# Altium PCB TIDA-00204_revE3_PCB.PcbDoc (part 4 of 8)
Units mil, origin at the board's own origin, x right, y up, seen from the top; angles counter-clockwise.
Board outline 4600 x 3740 mil, 8 copper layers (TopLayer - S1 (.GTL), MidLayer1 - S2 (.G1), MidLayer2 - S3 (.G2), MidLayer3 - S4 (.G3), MidLayer4 - S5 (.G4), MidLayer5 - S6 (.G5), MidLayer6 - S7 (.G6), BottomLayer - S8 (.GBL)), stack 58.938 mil thick; 536 components, 354 nets, 2015 pads, 1067 vias.
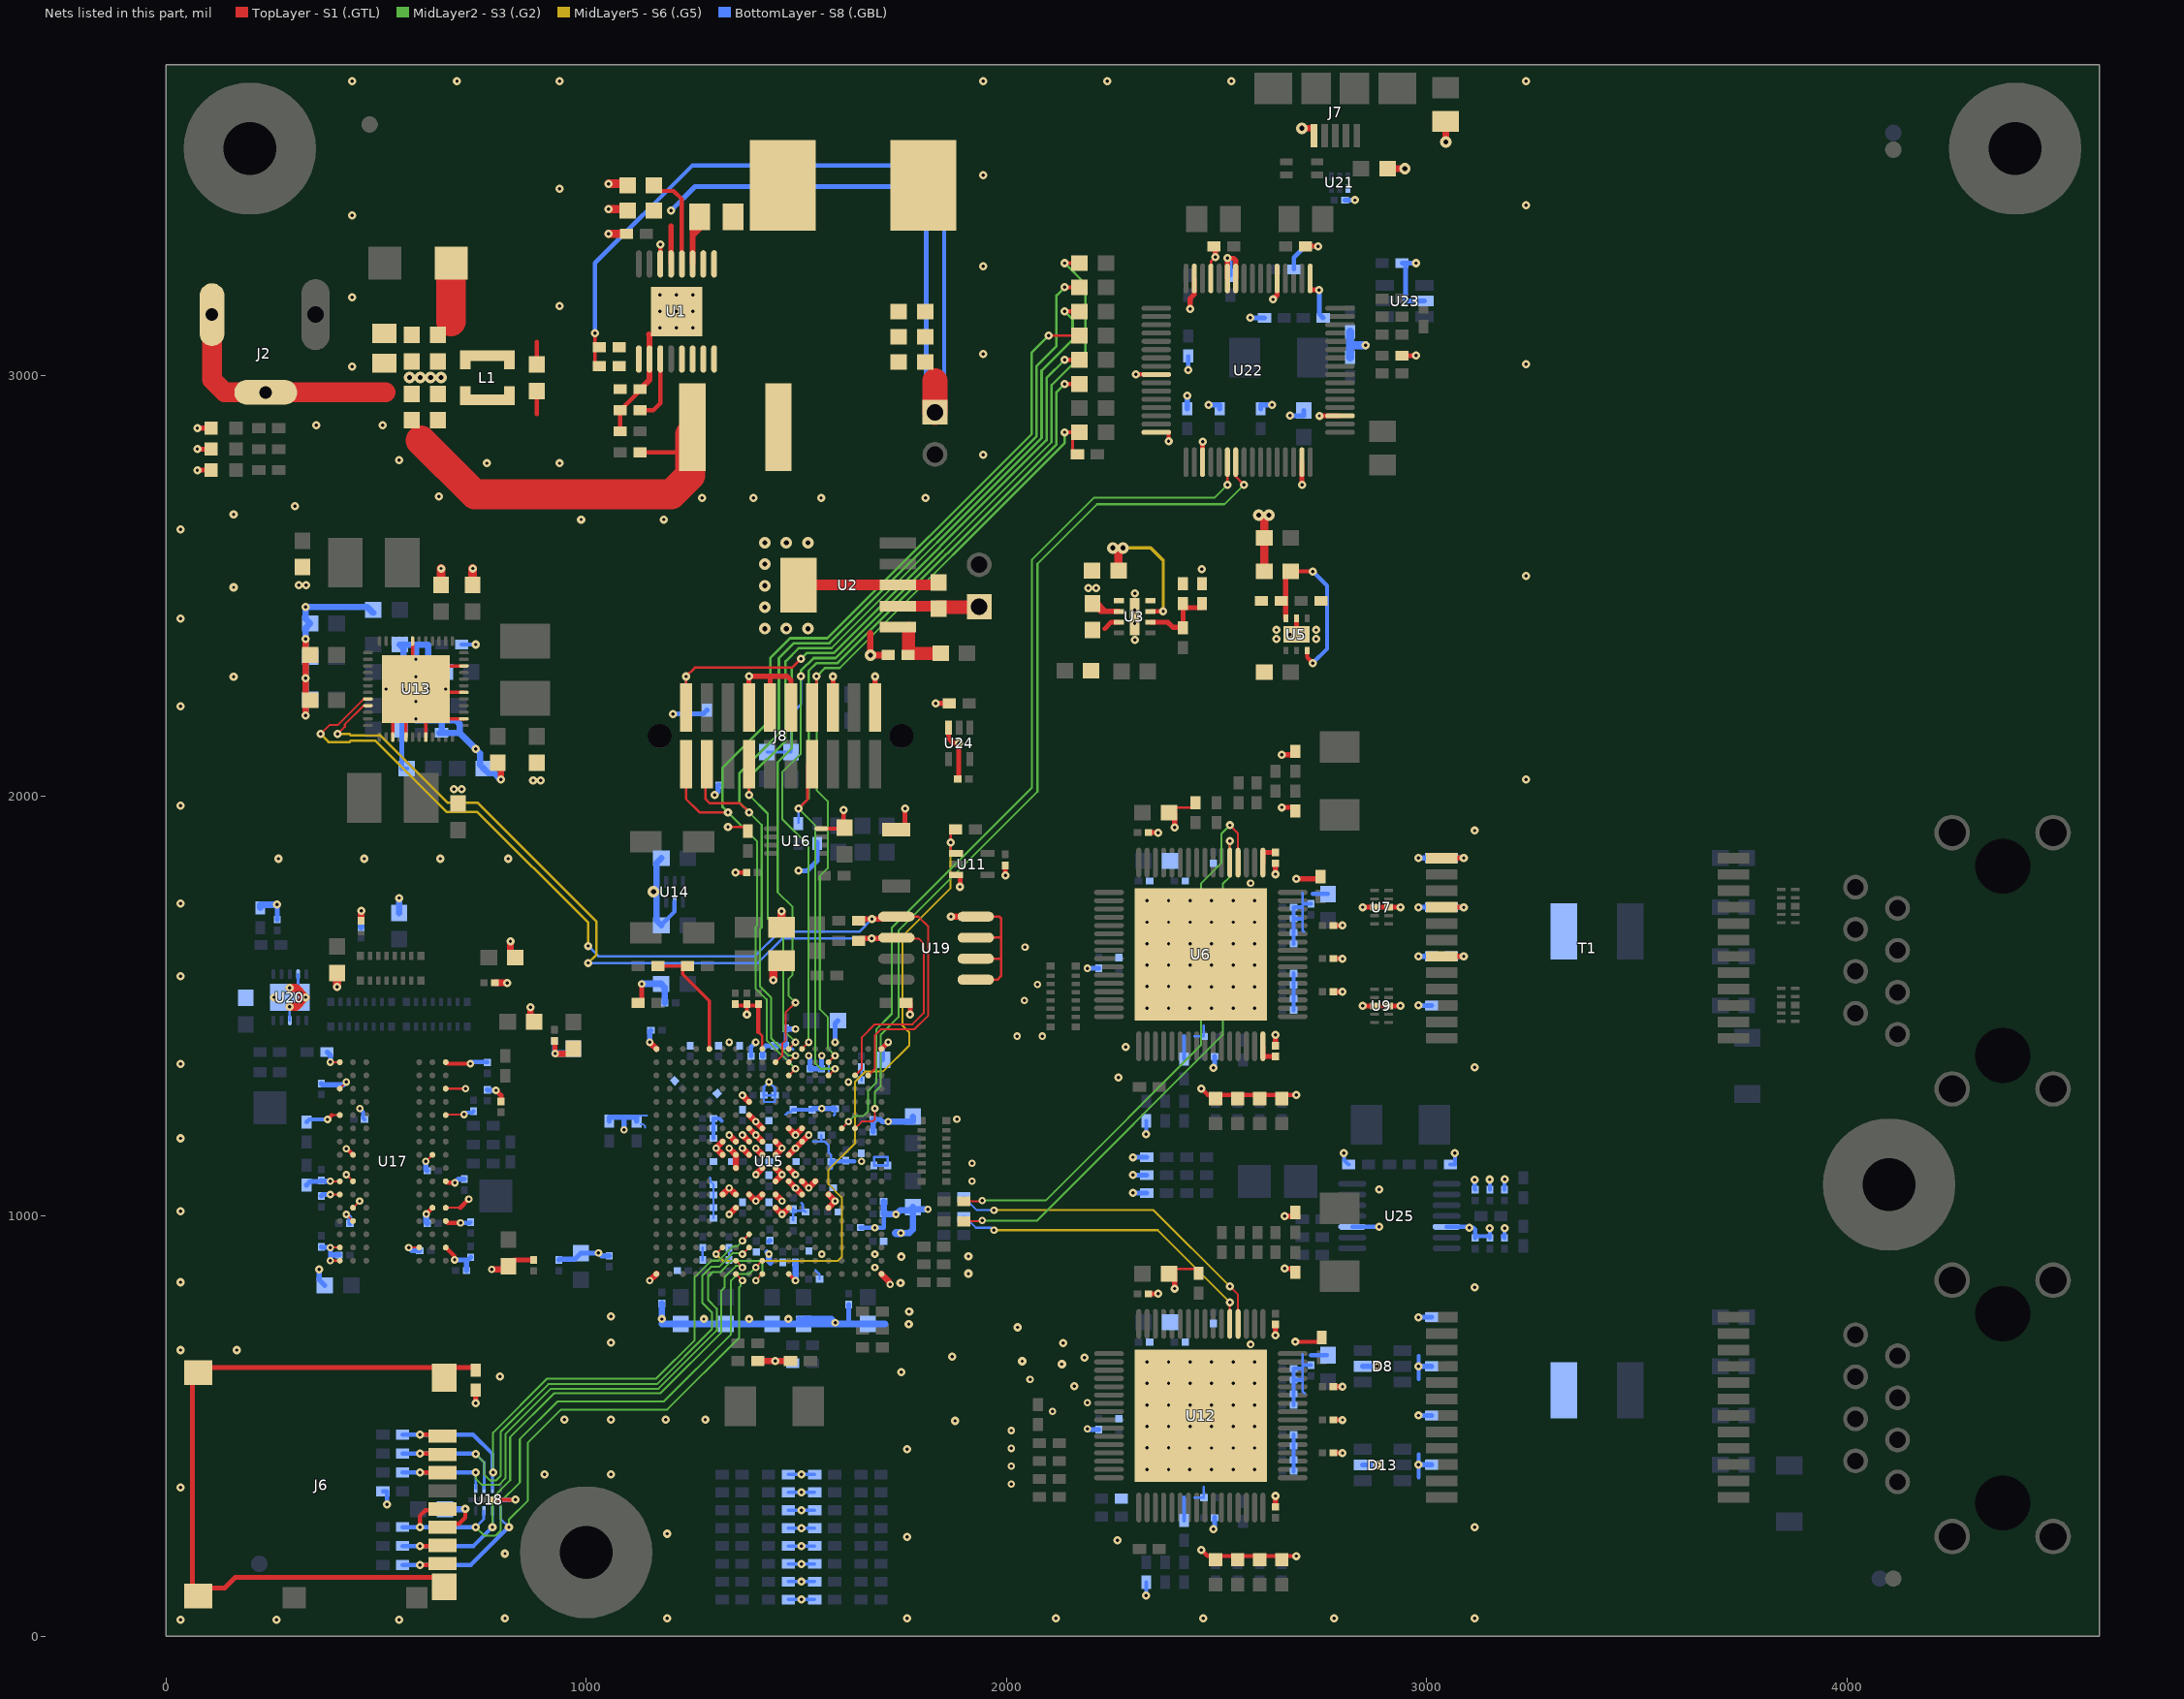
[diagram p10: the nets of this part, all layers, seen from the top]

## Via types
v1: diameter 19.68, hole 7.87, TopLayer - S1 (.GTL) to BottomLayer - S8 (.GBL), 600 vias
v2: diameter 17.72, hole 7.87, TopLayer - S1 (.GTL) to BottomLayer - S8 (.GBL), 408 vias
v3: diameter 27.56, hole 11.81, TopLayer - S1 (.GTL) to BottomLayer - S8 (.GBL), 31 vias
v4: diameter 20, hole 7.87, TopLayer - S1 (.GTL) to BottomLayer - S8 (.GBL), tented both sides, 11 vias
v5: diameter 15.75, hole 7.87, TopLayer - S1 (.GTL) to BottomLayer - S8 (.GBL), 9 vias
v6: diameter 20, hole 7.87, TopLayer - S1 (.GTL) to BottomLayer - S8 (.GBL), 5 vias
v7: diameter 15, hole 7.87, TopLayer - S1 (.GTL) to BottomLayer - S8 (.GBL), 2 vias
v8: diameter 18, hole 7.87, TopLayer - S1 (.GTL) to BottomLayer - S8 (.GBL), 1 vias

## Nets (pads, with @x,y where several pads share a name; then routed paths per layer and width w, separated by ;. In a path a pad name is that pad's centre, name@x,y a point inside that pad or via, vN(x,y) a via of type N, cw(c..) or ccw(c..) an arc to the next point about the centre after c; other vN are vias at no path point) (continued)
FTDI_UART3_RXD: U15.G15 U22.38 | length 2146.1
  TopLayer - S1 (.GTL) w4.75: U15.G15@1608.23,1208.76 v2(1623.98,1224.49)
  TopLayer - S1 (.GTL) w5.91: v1(2525.79,2739.96) U22.38@2525.79,2794
  MidLayer2 - S3 (.G2) w4.72: v2(1623.98,1224.49) 1637.68,1238.19 1659.45,1238.19 1671.26,1250 1671.26,1298.23 1689.96,1316.93 1689.96,1443.9 1727.36,1481.3 1727.36,1686.02 2060.04,2018.7 2060.04,2561.02 2208.66,2709.65 2495.47,2709.65 v1(2525.79,2739.96)
FTDI_UART3_TXD: U15.G16 U22.39 | length 2169.2
  TopLayer - S1 (.GTL) w4.75: U15.G16@1639.72,1208.76 1655.98,1225.02 1681.52,1225.02 1687,1230.5 v2(1686.97,1255.98)
  TopLayer - S1 (.GTL) w5.91: U22.39@2545.47,2794 2545.47,2759.65 v1(2564.96,2740.16)
  MidLayer2 - S3 (.G2) w4.72: v2(1686.97,1255.98) 1686.97,1295.24 1700.79,1309.06 1700.79,1431.1 1743.11,1473.43 1743.11,1679.13 2073.82,2009.84 2073.82,2552.17 2215.55,2693.9 2518.7,2693.9 v1(2564.96,2740.16)
GND: C1.2 C2.2 C3.2 C5.2 C6.2 C7.2 C8.2 C9.2 C10.2 C11.2 C12.2 C13.2 C15.2 C16.2 C17.2 C18.2 C21.2 C22.1 C23.2 C24.1 C25.2 C26.2 C27.2 C28.2 C29.2 C30.2 C31.2 C32.2 C34.2 C35.2 C36.2 C37.2 C38.2 C39.2 C40.2 C41.2 C42.2 C43.2 C44.2 C45.2 C46.2 C47.2 C48.2 C49.2 C50.2 C53.2 C54.2 C55.2 C56.2 C57.2 C58.2 C60.2 C61.2 C62.2 C63.2 C64.2 C65.2 C66.2 C67.2 C68.2 C69.2 C70.2 C71.2 C72.2 C73.2 C74.2 C75.2 C76.2 C77.2 C80.2 C81.2 C82.2 C83.2 C84.2 C85.2 C86.2 C87.2 C88.2 C89.2 C90.2 C91.2 C92.2 C93.2 C94.2 C95.2 C96.2 C97.2 C98.2 C99.2 C100.2 C101.2 C102.2 C103.2 C104.2 C105.1 C106.1 C107.1 C108.2 C109.2 C110.2 C111.1 C112.1 C113.1 C114.2 C115.2 C116.2 C117.1 C118.1 C119.1 C120.1 C121.1 C122.1 C123.1 C124.1 C125.1 C126.1 C127.2 C128.2 C129.2 C130.2 C131.2 C132.2 C133.2 C134.2 C135.2 C136.2 C137.2 C138.2 C139.2 C140.2 C141.2 C142.2 C143.2 C145.2 C146.2 C148.2 C149.2 C150.2 C151.2 C152.2 C153.2 C154.2 C155.2 C156.2 C157.2 C158.2 C159.2 C160.2 C161.2 C162.2 C163.2 C164.2 C165.2 C166.2 C167.2 C168.2 C169.2 C170.2 C171.2 C172.2 C173.2 C174.2 C175.2 C176.2 C177.2 C178.2 C179.2 C180.2 C181.2 C182.2 C183.2 C184.2 C185.2 C186.2 C187.2 C188.2 C189.2 C190.2 C191.1 C199.2 C200.2 C201.2 C202.2 C203.1 C205.2 C206.2 C207.1 C208.2 C209.2 C210.2 C211.2 C212.2 C213.2 C214.2 C215.2 C216.2 C217.2 C218.2 C219.2 C220.2 C221.2 C222.2 C223.2 C224.2 C225.2 C226.2 C227.2 C228.2 C229.2 C230.2 C231.2 C232.2 C233.2 C234.2 C235.2 C236.1 C237.1 C238.1 C239.1 C240.2 C241.2 C242.1 C243.1 C244.1 C245.1 C246.1 C247.1 C248.1 C249.1 C250.1 C251.2 C252.2 C253.2 C254.2 C255.2 C256.2 C257.2 C258.2 C259.2 C260.2 C261.1 C262.1 C263.1 C264.1 C265.1 C266.1 C267.1 C268.1 C271.1 C272.1 C273.1 C274.1 C275.1 C276.1 C277.1 C278.1 D2.2 D3.2 D4.2 D5.2 D6.2 D7.2 D8.2 D9.2 D10.2 D11.2 D12.2 D13.2 D14.2 J2.2 J2.3 J6.6 J7.5 J8.8 J8.10 J8.12 J8.16 J8.20 L7.2 L10.1 R4.1 R5.1 R7.1 R16.1 R21.1 R23.1 R31.1 R34.1 R41.1 R45.1 R57.2 R61.1 R62.1 R67.1 R68.1 R99.1 R101.1 R102.1 R103.1 R104.1 R105.1 R106.1 R107.1 R108.1 R109.1 R110.1 R111.1 R112.1 R113.1 R114.1 R115.1 R116.1 R119.1 R131.1 R132.1 R138.1 R151.1 R153.1 R157.1 R158.1 R165.1 R179.1 R180.1 R181.1 S1.1 U1.6 U1.10 U1.15 U1.16 U1.17 U2.3 U2.6 U3.4 U3.6 U3.9 U5.5 U5.7 U6.65 U7.3 U7.8 U9.3 U9.8 U11.3 U12.65 U13.15 U13.17 U13.20 U13.26 U13.30 U13.34 U13.43 U13.49 U14.2 U15.A1 U15.A18 U15.F8 U15.G8 U15.G9 U15.G11 U15.G12 U15.H6 U15.H7 U15.H8 U15.H9 U15.H10 U15.H12 U15.J6 U15.J7 U15.J8 U15.J9 U15.J10 U15.J11 U15.K7 U15.K9 U15.K10 U15.K11 U15.L10 U15.L11 U15.L12 U15.L13 U15.M6 U15.M7 U15.M8 U15.M9 U15.M10 U15.M12 U15.M14 U15.N7 U15.N10 U15.N11 U15.N14 U15.V1 U15.V18 U16.4 U17.A9 U17.B1 U17.B3 U17.B9 U17.D1 U17.D8 U17.E1 U17.E2 U17.E8 U17.F9 U17.G1 U17.G8 U17.G9 U17.J2 U17.J8 U17.M1 U17.M9 U17.P1 U17.P9 U17.T1 U17.T9 U18.5 U19.1 U19.2 U19.3 U19.4 U20.4 U20.8 U20.11 U21.4 U22.1 U22.5 U22.10 U22.11 U22.13 U22.15 U22.25 U22.32 U22.35 U22.47 U22.51 U23.2 U24.3 U25.5 U25.10 | length 18373.8
  TopLayer - S1 (.GTL) w5: v2(391.76,893.78) U17.A9@414.02,893.78 ; v2(391.76,925.28) U17.B9@414.02,925.28 ; v2(391.75,1051.26) U17.F9@414.02,1051.26 ; v2(391.76,1082.76) U17.G9@414.02,1082.76 ; v2(391.76,1366.22) U17.T9@414.02,1366.22 ; 395.24,1240.24 U17.M9@414.02,1240.24 ; U17.P9@414.02,1303.23 v2(429.76,1318.97) ; v2(429.76,1004.02) U17.D8@445.51,988.27 ; v2(429.76,1098.51) U17.G8@445.51,1082.76 ; v2(429.76,1160.43) v2@431.19,1159 ; U17.E8@445.51,1019.76 v2(461.26,1035.51) ; v2(577.79,925.28) U17.B3@602.99,925.28 ; v2(618.74,1130) U17.J2@634.49,1145.75 ; v2(620,1005) v2@620,1005.27 ; U17.D1@665.98,988.27 U17.D1@670.3,983.95 ; U17.E1@665.98,1019.76 700.35,1019.76 ; U17.G1@665.98,1082.76 U17.G1@669.61,1079.13 ; U17.P1@665.98,1303.23 v2(712.96,1303.23) ; U17.T1@665.98,1366.22 U17.T1@669.61,1362.59 ; U17.M1@667.43,1241.69 v2(709.57,1241.69) ; v2(687.15,895.77) v2@687.15,904.11
  TopLayer - S1 (.GTL) w5.91: U19.1@1926.99,1562.5 1978.84,1562.5 1987.2,1570.87 1987.2,1708.66 1983.37,1712.5 U19.4@1926.99,1712.5 ; U19.2@1926.99,1612.5 1986.52,1612.5 ; U19.3@1926.99,1662.5 1986.5,1662.5 ; U22.13@2486.42,3231 2486.42,3270.87 v1(2497.05,3281.5)
  TopLayer - S1 (.GTL) w6: v1(1337.6,1926.18) 1385,1926.18 R119.1@1385,1916.12 ; C67.2@2400,862.5 2400,874.5 2457.5,874.5 R45.1@2457.5,863.62 ; C40.2@2400,1960 2400,1972 R23.1@2446.5,1972
  TopLayer - S1 (.GTL) w8: U13.15@539.88,2139.83 539.88,2184 571.38,2184 U13.17@571.38,2139.83 ; U13.43@587.13,2368.17 587.13,2309.12 U13.34@709.17,2309.12 ; U13.20@618.62,2139.83 618.62,2183.13 U13.26@709.17,2183.13 ; U13.49@660,2246.13 U13.30@709.17,2246.13
  TopLayer - S1 (.GTL) w9.84: v1(2307.78,3002.66) U22.25@2356.5,3002.66 ; U22.32@2328.44,2864.86 U22.32@2356.5,2864.86 2385.83,2864.86 v1(2385.83,2843.5) ; v1(2687.01,700.79) 2739.67,700.79 R41.1@2750,711.12
  TopLayer - S1 (.GTL) w10: v2(385,1230) 395.24,1240.24 ; v2@431.19,1159 432.26,1159 U17.J8@445.51,1145.75 ; v2@620,1005.27 U17.E2@634.49,1019.76 ; J6.6@658.56,259.63 666.44,267.5 697.62,267.5 712.6,282.48 v1(712.6,303.15) ; U17.B1@665.98,925.28 v2@687.15,904.11 ; U17.M1@665.98,1240.24 U17.M1@667.43,1241.69 ; U17.G1@669.61,1079.13 v2(687.73,1079.13) ; U17.T1@669.61,1362.59 v2(725,1362.59) ; U17.D1@670.3,983.95 v2(701.2,983.95) ; 700.35,1019.76 v2(720.83,1040.24) ; C205.2@780.28,325 v1(831.78,325) ; R4.1@1081.38,2867.5 C12.2@1081.38,2917.5 1128.62,2964.74 R7.1@1128.62,2967.5 ; U1.6@1176.61,3265.69 v1(1176.61,3311.45) v1@1176.61,3315.39 ; v1(1355.5,1817.5) C200.2@1382.01,1817.5 ; v1(1465,1725.5) v1@1465.5,1726 ; U16.4@1560.04,1922.03 C201.2@1612.2,1922.03 ; v1(1612.2,1966.54) C201.2@1612.2,1922.03 ; C201.2@1615,1916.12 1612.2,1916.12 C201.2@1612.2,1922.03 ; v1(2464,205.5) 2478.5,191 D12.2@2497.5,191 ; v1(2464,1303) 2478.5,1288.5 D7.2@2497.5,1288.5 ; D12.2@2497.5,182.03 D12.2@2497.5,191 ; D7.2@2497.5,1279.53 D7.2@2497.5,1288.5 ; D11.2@2655,182.03 D11.2@2655,191 ; D6.2@2655,1279.53 D6.2@2655,1288.5 ; v1(2689.5,191) D11.2@2655,191 ; v1(2689.5,1288.5) D6.2@2655,1288.5 ; D12.2@2497.5,191 D11.2@2655,191 ; D7.2@2497.5,1288.5 D6.2@2655,1288.5
  TopLayer - S1 (.GTL) w11.81: v1(75,2775) D14.2@107.97,2775 ; v1(75,2825) D3.2@107.97,2825 ; v1(75,2875) D2.2@107.97,2875 ; v1(737.5,555) C206.2@737.5,586.38 ; v2(785.43,1299.21) 797.5,1287.15 C166.2@797.5,1272.99 ; C168.2@925,1417.01 926.18,1417.01 v2(926.18,1386.81) ; R68.1@1123.88,1507.5 1132.22,1515.85 v2(1132.22,1552.5) ; J8.8@1387.5,2210.04 1387.5,2284.45 v1(1387.8,2284.45) 1437.5,2284.45 ; J8.10@1437.5,2210.04 1437.5,2284.45 ; J8.12@1487.5,2210.04 1487.5,2275.3 1478.35,2284.45 1437.5,2284.45 ; J8.16@1587.5,2210.04 v1(1587.5,2283.96) ; J8.20@1687.5,2210.04 v1(1687.5,2283.96) ; S1.1@1737.5,1919.43 1758.86,1919.43 v1(1758.86,1969.49) ; v1(1831.69,2220) R165.1@1863.88,2220 ; U24.3@1861.91,2162.4 1861.91,2137.11 1874.02,2125 v1(1886.81,2125) 1886.81,2042.3 C243.1@1884.51,2040 ; U11.3@1880.1,1811.91 1889.76,1811.91 v1(1889.76,1783.46) ; v1(1997.5,1810.57) C35.2@1997.5,1834.51 ; v1(2437.01,3158.46) 2437.01,3183.07 2447.05,3193.11 U22.15@2447.05,3231 ; U22.35@2466.73,2794 v1(2466.73,2842.72) ; C237.1@2493.88,3307.5 2497.05,3304.33 v1(2497.05,3281.5) ; U22.11@2525.79,3231 v1(2525.79,3279.33) 2540.55,3279.33 2545.47,3274.41 U22.10@2545.47,3231 ; v1(2633.86,3181.1) 2643.9,3191.14 U22.5@2643.9,3231 ; v1(2689.96,1802.56) 2742.48,1802.56 R21.1@2747.5,1807.58 ; v1(2702.95,2740.35) U22.47@2702.95,2794 ; C236.1@2711.12,3307.5 v1(2741.71,3307.5) ; U22.1@2722.64,3231 2722.64,3203.74 v1(2744.09,3203.74) ; v1(2744.39,2904.23) U22.51@2793.5,2904.23 ; R158.1@2941.12,3047.5 v1(2974.41,3047.5)
  TopLayer - S1 (.GTL) w12: C231.2@815,881 829.49,895.49 C161.2@875,895.49 ; U15.A18@1702.72,1397.77 v2(1718.46,1413.46) ; C207.1@1761.12,1507.5 1771,1507.5 v1(1771,1480) ; C17.2@2205,2457.5 2223.7,2438.8 2236.4,2438.8 ; C17.2@2212.6,2462.6 2236.4,2438.8 ; U3.6@2267.6,2438.8 2236.4,2438.8 ; C68.2@2338.5,815 v1(2361,815) ; C41.2@2338.5,1912.5 v1(2361,1912.5) ; v1(2400,827.5) C67.2@2400,862.5 ; v1(2400,1925) C40.2@2400,1960 ; C54.2@2640,307.99 v1(2640,334) ; v1(2640,716) C53.2@2640,742.01 ; C26.2@2640,1405.49 v1(2640,1431.5) ; v1(2640,1813.5) C25.2@2640,1839.51 ; v1(2655,1972.5) 2678.88,1972.5 C31.2@2687.5,1963.88 ; v1(2655,2097.5) 2678.88,2097.5 C32.2@2687.5,2106.12 ; v1(2662,875) 2678.88,875 C60.2@2687.5,866.38 ; v1(2662,1000) 2678.88,1000 C61.2@2687.5,1008.62 ; U5.7@2690,2384 U5.5@2690,2422.39 ; C66.2@2777.99,436.42 v1(2799.6,436.42) ; C74.2@2777.99,515 v1(2799.6,515) ; C65.2@2777.99,593.9 v1(2799.6,593.9) ; C38.2@2777.99,1533.92 v1(2799.6,1533.92) ; C47.2@2777.99,1612.5 v1(2799.6,1612.5) ; C39.2@2777.99,1691.4 v1(2799.6,1691.4) ; v1(2847.5,1500) U9.8@2875.77,1500 U9.3@2909.23,1500 v1(2937.5,1500) ; v1(2847.5,1735) U7.8@2875.76,1735 U7.3@2909.23,1735 v1(2937.5,1735)
  TopLayer - S1 (.GTL) w14: R7.1@1128.62,2967.5 1151.02,2989.9 U1.10@1151.02,3039.31 1151.02,3096.48 1150,3097.5 ; U1.17@1176.61,3190.89 v5(1215,3152.5)
  TopLayer - S1 (.GTL) w15: v1(333,2191) v1(333,2280) v1(333,2373) ; v2(775.5,873) 807,873 C231.2@815,881 ; v1(797,2038.5) C97.2@797,2077 ; v2(926.18,1386.81) C232.2@957.5,1386.81 ; v2(1151.54,1413.46) v2(1151.54,1413.46) U15.A1@1167.28,1397.72 ; v2(1151.58,846.49) U15.V1@1167.28,862.28 ; U15.M6@1324.76,1051.26 v2(1340.51,1067.01) U15.M7@1356.24,1051.28 ; U15.J6@1324.76,1145.77 v2(1309.02,1161.5) U15.H6@1324.75,1177.26 ; v2(1340.51,1004.02) U15.N7@1356.26,1019.76 ; v2(1340.51,1161.5) 1356.26,1145.77 U15.K7@1356.26,1114.25 ; v2(1340.51,1192.99) U15.H7@1356.26,1177.26 ; v2(1372.01,1161.5) U15.J8@1387.76,1145.77 ; v2(1372.01,1192.99) U15.H8@1387.76,1177.26 ; U15.M8@1387.76,1051.26 v2(1403.5,1035.51) U15.M9@1419.25,1051.28 ; U15.G8@1387.76,1208.75 U15.H9@1419.25,1177.26 ; U15.F8@1387.76,1240.26 v2(1403.5,1224.49) U15.G9@1419.25,1208.76 ; v2(1403.5,1098.5) U15.K9@1419.25,1114.27 ; v2(1403.5,1161.5) U15.J9@1419.25,1145.77 ; U15.N10@1450.76,1019.77 v2(1466.5,1004.02) U15.N11@1482.24,1019.76 ; U15.M10@1450.76,1051.27 v2(1466.5,1035.51) ; U15.L10@1450.76,1082.78 v2(1466.5,1098.5) U15.K10@1450.75,1114.25 ; U15.J10@1450.75,1145.77 v2(1466.5,1161.5) U15.H10@1450.76,1177.26 ; U15.L11@1482.24,1082.76 U15.M12@1513.74,1051.26 ; U15.K11@1482.25,1114.26 v2(1497.99,1098.5) ; U15.J11@1482.24,1145.77 v2(1497.99,1161.5) v2(1529.49,1192.99) ; U15.G11@1482.26,1208.76 v2(1497.99,1192.99) U15.G12@1513.74,1208.76 ; U15.L12@1513.74,1082.76 v2(1529.49,1067.01) U15.L13@1545.24,1082.76 ; U15.N14@1576.73,1019.76 v2(1592.48,1035.51) ; U15.M14@1576.73,1051.26 v2(1592.48,1035.51) ; U15.V18@1702.72,862.28 v2@1720,845.02
  TopLayer - S1 (.GTL) w15.75: C228.2@465,1702.99 v1(465,1726.38) ; C229.2@782.99,1555 v1(812.01,1555) ; v1(819.88,1653.54) 819.88,1615 C225.2@831.5,1615 ; v1(867.5,1497.05) 867.5,1462.5 C211.2@876.5,1462.5 ; 1676.18,2386.81 v3(1676.18,2335) C15.2@1718.88,2335 ; v1(1868.01,1712.5) U19.4@1926.99,1712.5 ; v3(2702.76,3588.58) 2731.32,3588.58 J7.5@2731.32,3570.71 ; C234.2@2906.5,3492.5 v3(2947.83,3492.5) ; v3(3045,3556.1) L10.1@3045,3605
  TopLayer - S1 (.GTL) w19.68: v1(295,1497.86) 309.76,1497.86 v1(332.4,1520.5) 309.76,1543.14 v1(295,1543.14) ; v1(407.5,1545.5) C227.2@407.5,1578.5
  TopLayer - S1 (.GTL) w20: C81.2@655,2514 v1(655,2541) ; C80.2@730,2514 v1(730,2541) ; v1(1053.15,3337.5) R5.1@1096.38,3337.5 ; v1(1053.15,3396.44) C10.2@1098.5,3396.44 ; v1(1053.15,3456.44) C13.2@1098.5,3456.44 ; L7.2@1465,1687.5 v1(1465,1725.5)
  TopLayer - S1 (.GTL) w25: U2.6@1505.39,2501.5 U2.3@1741.61,2501.5 1832.01,2501.5 C16.2@1838.5,2507.99
  TopLayer - S1 (.GTL) w47.24: J2.2@110,3145 110,2990 140.04,2959.96 J2.3@238,2959.96 522.46,2959.96
  BottomLayer - S8 (.GBL) w4.72: R99.1@1120,1235 1124.17,1239.17 1145.47,1239.17 ; R99.1@1129.53,1218.7 1135.63,1218.7 1140.75,1213.58 1140.75,1210.63 ; 1293.7,1092.13 1296.46,1089.37 1296.46,1081.54 C150.2@1302.99,1075 C152.2@1302.99,1050 C154.2@1302.99,1020 C153.2@1302.99,995 ; C127.2@1422.99,1287.5 1422.99,1271.26 1449.51,1271.26 C132.2@1449.51,1287.5 ; 1422.99,1303.15 1423.23,1303.15 ; 1577.17,1367.52 1577.17,1336.02 1578.74,1334.45
  BottomLayer - S8 (.GBL) w5: v2(725,1362.59) v2@728.75,1366.34
  BottomLayer - S8 (.GBL) w5.51: 1474.41,1241.54 1479.72,1246.85 1486.36,1246.85 C188.2@1492.5,1252.99 ; 1539.96,1177.17 1568.11,1177.17 1576.57,1168.7 1576.57,1151.57 1582.99,1145.16 C190.2@1582.99,1130 1585,1132.01 C111.1@1617.5,1132.01 ; 1546.06,870.47 1555.49,861.04 C109.2@1555.49,850 ; 1559.51,1178.29 C122.1@1559.51,1192.5
  BottomLayer - S8 (.GBL) w5.91: C103.2@1277.5,895.49 C117.1@1277.5,925 ; C118.1@1340,895.49 C102.2@1340,924.51 ; C140.2@1475,1405.49 1475,1399.41 1489.76,1399.41 1492.13,1397.05 ; C105.1@1492.5,990.49 C172.2@1492.5,1017.01 1496.71,1012.8 C174.2@1519.21,1012.8 ; 1511.81,1031.3 1516.14,1026.97 1516.14,1015.87 C174.2@1519.21,1012.8 ; C174.2@1522.01,1010 C174.2@1519.21,1012.8 ; C125.1@1562.5,1350.49 1576.57,1350.49 ; 1589.37,1239.96 1592.01,1242.6 C123.1@1592.01,1255 ; C128.2@1655,1322.99 C191.1@1655,1354.51 ; 2705,671.5 2705,582.5 2709.5,578 ; 2705,1769 2705,1679.5 2708,1676.5 ; C114.2@1685,1120.49 C115.2@1717.5,1120.49 1717.5,1140.77 1685,1140.77 C114.2@1685,1120.49
  BottomLayer - S8 (.GBL) w6: U20.8@295,1465.38 v1(295,1497.86) U20.11@295,1499 ; U20.11@314.68,1545 U20.4@314.68,1575.62 ; 2447,330 C77.2@2469.51,330 2469.51,355.49 ; 2447,1427.5 C50.2@2469.51,1427.5 2469.51,1452.99 ; C127.2@1422.99,1287.5 1422.99,1303.15 1422.99,1306.97 v2(1435,1318.98) 1449.51,1304.47 C132.2@1449.51,1287.5 C127.2@1422.99,1287.5
  BottomLayer - S8 (.GBL) w7.87: 561.5,2186.04 595,2186.04 v1(595,2183.13) v1@595,2179.63
  BottomLayer - S8 (.GBL) w8: R116.1@1481.12,87.5 v1(1512.5,87.5) R115.1@1543.88,87.5 ; R114.1@1481.12,130 v1(1512.5,130) R113.1@1543.88,130 ; R112.1@1481.12,172.5 v1(1512.5,172.5) R111.1@1543.88,172.5 ; R110.1@1481.12,215 v1(1512.5,215) R109.1@1543.88,215 ; R108.1@1481.12,257.5 v1(1512.5,257.5) R107.1@1543.88,257.5 ; R106.1@1481.12,300 v1(1512.5,300) R105.1@1543.88,300 ; R104.1@1481.12,342.5 v1(1512.5,342.5) R103.1@1543.88,342.5 ; R102.1@1481.12,385 v1(1512.5,385) R101.1@1543.88,385
  BottomLayer - S8 (.GBL) w9.84: v2(461.61,1255.91) 469.49,1248.03 469.49,1233.5 C208.2@472.99,1230 ; C157.2@1302.99,1185 C159.2@1302.99,1209 C155.2@1302.99,1232.5 1316.53,1232.5 1322.65,1226.38 ; C140.2@1475,1405.49 C186.2@1475,1447.01 C186.2@1475,1448.43 ; C188.2@1492.5,1252.99 C189.2@1537.5,1252.99 ; 1582.99,1115.53 C190.2@1582.99,1130 1637.87,1130 ; v1(2432.5,3012.8) C244.1@2432.5,3046.38 ; C271.1@2682.99,392.5 C272.1@2682.99,420 C273.1@2682.99,452.5 C274.1@2682.99,480 ; C275.1@2682.99,550 C276.1@2682.99,577.5 C277.1@2682.99,610 ; C261.1@2682.99,1490 C262.1@2682.99,1517.5 C263.1@2682.99,1550 C264.1@2682.99,1577.5 ; C265.1@2682.99,1647.5 C266.1@2682.99,1675 C267.1@2682.99,1707.5 ; 2702.5,1735 C268.1@2682.99,1735 C267.1@2682.99,1707.5 ; 2703,610 C277.1@2682.99,610 ; 2703,637.5 C278.1@2682.99,637.5 C277.1@2682.99,610 ; 2703,1707.5 C267.1@2682.99,1707.5 ; 2706.99,645.49 C64.2@2725,645.49 ; 2707.01,1742.99 C37.2@2725,1742.99 ; 2724.45,669 C63.2@2762.5,669 ; 2728.5,1766.5 C36.2@2765,1766.5 ; v1(2803,1149.5) 2803,1133.38 C259.2@2813.88,1122.5 ; v1(2886.5,974.5) U25.10@2822.89,974.5 ; 2980.58,378.22 v1(2980.58,408.58) 2980.58,433.34 ; 2980.58,612.08 v1(2980.58,642.44) 2980.58,667.2 ; U25.5@3047.2,974.41 3099.09,974.41 v1(3101,972.5) 3110.5,972.5 3115,968 C257.2@3115,952 ; C258.2@3056.12,1122.5 3067,1122.5 v1(3067,1149.5) ; v1(3114.17,1086.61) 3114.17,1063.82 C253.2@3115,1062.99 ; C257.2@3115,947.99 C257.2@3115,952 ; C256.2@3150,947.99 C256.2@3150,952 ; v1(3150,971) C256.2@3150,952 ; C254.2@3150,1062.99 v1(3150,1087) ; C255.2@3180.99,952 C255.2@3185,947.99 v1(3185,971) ; C252.2@3185,1062.99 v1(3185,1087.5) ; U25.10@2822.89,974.5 U25.10@2822.8,974.41 2822.8,974.5 U25.10@2822.89,974.5 ; C257.2@3115,952 C256.2@3150,952
  BottomLayer - S8 (.GBL) w10: R132.1@335,1223.62 341.38,1230 v2(385,1230) ; C203.1@516.38,345 526,345 v1(526,314) ; C98.2@562.01,2065 C98.2@573.5,2065 ; C85.2@562.01,2209.49 561.5,2210 C85.2@556.5,2215 561.5,2215 595,2215 C87.2@633.5,2215 ; v2(701.2,983.95) 723.46,983.95 C214.2@725,985.49 ; R67.1@703.62,2360 v1(737,2360) ; v2(709.57,1241.69) 713.94,1246.06 728.93,1246.06 C169.2@732.25,1249.38 ; v2@728.75,1366.34 C165.2@765.47,1366.34 ; U18.5@802.72,325 v1(831.78,325) ; C101.2@1178.98,1691.69 1178.98,1693.2 1210.47,1724.69 U14.2@1210.47,1748.07 ; C137.2@1652.99,972.5 v2(1686.97,972.52) 1707.99,972.52 C135.2@1707.99,1005 ; v1(2332.5,97) R61.1@2332.5,128.88 ; v1(2332.5,1194.5) R31.1@2332.5,1226.38 ; R62.1@2422.5,276.12 2422.5,330 ; R34.1@2422.5,1373.62 2422.5,1427.5 ; R157.1@2683.62,3252.5 2683.62,3280.62 2710.5,3307.5 v1(2741.71,3307.5)
  BottomLayer - S8 (.GBL) w11.81: C210.2@265,1705.49 v1(265,1741.14) v1@265.75,1741.14 ; C85.2@561.5,2215 561.5,2210 561.5,2186.04 561.5,2065 C98.2@562.01,2065 ; C160.2@765,1300.49 766.28,1299.21 v2(785.43,1299.21) ; v2@925,1386.81 C162.2@925,1417.01 ; v1(1206.69,2194.88) 1278.5,2194.88 R151.1@1287.5,2203.88 ; v1(1306.1,2001.97) 1313.98,2009.84 1313.98,2025 C238.1@1317.01,2025 ; v1(1504.92,1821.85) 1526.57,1821.85 1550,1845.28 C242.1@1550,1886.38 C242.1@1550,1888.88 ; v2(1592.5,746.06) 1625,746.06 ; C178.2@1625,789.51 1625,746.06 ; C170.2@1670,743.5 1670,746.06 1625,746.06 ; v1(2301,1055) R179.1@2333.88,1055 ; v1(2301,1097.5) R180.1@2333.88,1097.5 ; v1(2301,1140) R181.1@2333.88,1140 ; C245.1@2430,2921.12 v1(2430,2951.77) ; v1(2481.3,2930.12) 2507.5,2930.12 C248.1@2507.5,2921.12 ; v1(2525.79,3279.33) 2532.5,3272.62 C249.1@2532.5,3238.62 ; v1(2580.02,3137.5) C241.2@2613.88,3137.5 ; C246.1@2605,2921.12 2605,2930.12 v1(2631.89,2930.12) ; v1(2674.21,2904.53) 2707.5,2904.53 C251.2@2707.5,2916.5 ; v1(2744.09,3203.74) 2744.09,3147.03 C240.2@2753.62,3137.5 ; C235.2@2805.49,3417.5 v1(2828.74,3417.5) ; C239.1@2941.12,3267.5 C239.1@2949.8,3267.5 ; v1(2974.41,3267.5) C239.1@2949.8,3267.5 ; U23.2@2994.74,3177.5 2949.8,3177.5 C239.1@2949.8,3267.5
  BottomLayer - S8 (.GBL) w12: R131.1@335,1073.88 343.62,1082.5 367.99,1082.5 C224.2@370,1084.51 371.75,1082.76 v2(391.76,1082.76) ; v1(365,873) 365,848.5 C212.2@378.5,835 ; C215.2@370,927.01 371.73,925.28 v2(391.76,925.28) v2(391.76,893.78) ; C217.2@370,1047.99 373.27,1051.26 v2(391.75,1051.26) ; C216.2@370,1315.49 372.99,1312.5 423.29,1312.5 v2(429.76,1318.97) ; C209.2@383.62,1390 391.76,1381.86 v2(391.76,1366.22) ; 395,907.5 C223.2@412.01,907.5 ; v2(429.76,1004.02) 437.99,995.79 C222.2@437.99,982.5 ; v2(577.79,925.28) 585.57,917.5 C219.2@604.51,917.5 ; v2(618.74,1130) 618.74,1110.77 C220.2@622.01,1107.5 ; v2(687.15,895.77) 718.76,895.77 C164.2@725,902.01 ; v2(687.73,1079.13) 696.59,1087.99 C221.2@710,1087.99 ; C218.2@715.49,870 715.49,893.51 ; C167.2@935,895.49 937.01,897.5 973.5,897.5 C148.2@987.5,911.5 1028.5,911.5 v2(1029.5,912.5) 1036.51,905.49 C163.2@1055,905.49 ; C199.2@1055,1226.12 1055,1235 1090,1235 ; v2(1090,1205) 1090,1235 ; R99.1@1120,1226.12 1120,1235 1090,1235 ; v2(1151.54,1413.46) 1151.54,1439.53 C187.2@1154.51,1442.5 ; C139.2@1420,1380.49 1420,1397.5 1427.99,1405.49 C141.2@1447.5,1405.49 C140.2@1475,1405.49 ; v2@1430.02,914.51 v2(1435,909.53) ; C106.1@1435,939.51 C106.1@1437.5,942.01 ; C186.2@1475,1448.43 1478.46,1444.96 v2(1497.99,1444.96) ; v2(1529.49,1381.97) 1532.5,1378.96 C124.1@1532.5,1350.49 C125.1@1560,1350.49 ; C189.2@1537.5,1252.99 1540.49,1255.98 v2(1560.98,1255.98) 1591.02,1255.98 C123.1@1592.01,1255 ; v2@1560,1380.45 C125.1@1560,1350.49 ; v2(1560.98,1381.97) v2@1562.5,1380.45 ; C125.1@1562.5,1350.49 C125.1@1560,1350.49 ; v2(1592.48,1413.46) 1592.48,1458.48 C185.2@1599,1465 ; C133.2@1682.99,1200 C121.1@1682.99,1230 1699.53,1230 1705.04,1224.49 v2(1718.46,1224.49) ; C131.2@1705,1371.5 1705,1400 v2(1718.46,1413.46) ; v2@2198.51,492.01 C70.2@2220,492.01 ; v2@2198.51,1589.51 C43.2@2220,1589.51 ; v1(2492,255) 2495.49,258.49 C71.2@2495.49,282.5 ; v1(2492,1352.5) 2495.49,1355.99 C44.2@2495.49,1380 ; D13.2@2847.76,407.82 v1(2882.5,407.82) ; D8.2@2847.76,642.5 v1(2882.5,642.5) ; v1(2980.58,408.58) C58.2@3011.34,408.58 ; v1(2980.58,525.51) C57.2@3011.34,525.51 ; v1(2980.58,642.44) C56.2@3011.34,642.44 ; v1(2980.58,759.37) C55.2@3011.34,759.37 ; v1(2980.58,1501.08) C30.2@3011.34,1501.08 ; v1(2980.58,1618.01) C29.2@3011.34,1618.01 ; v1(2980.58,1734.94) C28.2@3011.34,1734.94 ; v1(2980.58,1851.87) C27.2@3011.34,1851.87
  BottomLayer - S8 (.GBL) w15: v1(333,2191) 333,2219.5 C92.2@343.5,2230 333,2240.5 v1(333,2280) v1(333,2373) 333,2399.5 C96.2@343.5,2410 333,2420.5 v1(333,2449) 479.5,2449 C95.2@493.5,2435 ; C85.2@556.5,2215 565.47,2223.98 v1(565.47,2254) ; C82.2@556.5,2295 C82.2@565.47,2295 ; v1@595,2179.63 633.5,2179.63 ; v1@595,2186.04 595,2215 v1(595,2224.47) 595,2254 ; v2(620,1005) 620,984.51 C213.2@622.01,982.5 ; C99.2@651.12,2150 C99.2@656.12,2150 ; C202.2@663.78,302.5 711.95,302.5 v1(712.6,303.15) ; v1(665.87,2254) v1@663.5,2254 ; v1(797,2038.5) 781.5,2054 767.5,2054 C84.2@756.5,2065 748,2073.5 748,2101 v1(737,2112) 699,2150 ; C101.2@1178.98,1691.69 1167.47,1703.2 1167.47,1840.19 C100.2@1178.98,1851.69 ; v1(1180,755) C119.1@1180,792.01 ; v2(1435,909.53) 1435,893 1438.49,889.51 ; C110.2@1506,755 C110.2@1517.5,743.5 1517.5,754.92 1583.64,754.92 v2(1592.5,746.06) ; C136.2@1707.99,1035 C135.2@1707.99,1005 1736,1005 v2(1737,1004) 1747,1014 1770.5,1014 C116.2@1777.5,1021 ; v2(1718.46,1224.49) 1777.5,1224.49 C113.1@1777.5,1236.5 ; v1(565.47,2254) 595,2254 ; v1(565.47,2254) C82.2@565.47,2295 ; C82.2@565.47,2295 565.47,2351.02 C83.2@556.5,2360 595,2360 ; C82.2@565.47,2295 595,2295 ; 595,2254 v1(595,2283.53) 595,2295 ; 595,2254 v1(624.53,2254) ; 595,2295 v1(595,2324.87) 595,2360 ; 595,2295 624.53,2295 ; 595,2360 624.53,2360 624.53,2295 ; v1(624.53,2254) v1@633.5,2254 ; v1(624.53,2254) 624.53,2295 ; 624.53,2295 C91.2@663.5,2295 v1@663.5,2254 ; 633.5,2179.63 C87.2@633.5,2215 v1@633.5,2254 ; 633.5,2179.63 656.12,2179.63 ; v1@633.5,2254 v1@663.5,2254 ; C99.2@656.12,2150 656.12,2179.63 ; C99.2@656.12,2150 699,2150 ; 656.12,2179.63 690.37,2179.63 699,2171 699,2150
  BottomLayer - S8 (.GBL) w15.75: R138.1@225,1733.62 225,1741.14 v1(265,1741.14) ; C230.2@465,1687.99 v1(465,1726.38) ; v1(524.13,2254) v1(565.47,2254) ; C226.2@555,1721.5 v1(555,1756.89) ; v2@925,1386.81 v2(926.18,1386.81) 970,1386.81 C149.2@970,1398.5 ; v2(1132.22,1552.5) C171.2@1178.5,1552.5 1187.01,1544 C179.2@1187.01,1507.5 ; 1180.31,743.5 C126.1@1225,743.5 C107.1@1442.5,743.5 1711.02,743.5 ; v2(1749.02,959.65) 1768.7,959.65 1777.5,968.44 C116.2@1777.5,1021 ; C116.2@1780.03,1016.25 v2(1813,1016.25)
  BottomLayer - S8 (.GBL) w19.68: 1737.2,959.65 v2(1749.02,959.65) ; C247.1@2817.5,3043.62 C250.1@2817.5,3103.88 ; 2818.9,3071.85 v1(2854.33,3071.85)
  other v1: 35.43,39.37 263.78,39.37 555.12,39.37 807.09,43.31 1192.91,43.31 1763.78,43.31 2118.11,43.31 2468.5,43.31 2779.53,43.31 3114.17,43.31 807.09,196.85 2263.78,228.35 1763.78,236.22 1192.91,244.09 3114.17,259.84 35.43,354.33 901.57,385.83 1059.06,385.83 2334.55,397.05 2385.73,397.05 2435.93,397.05 2488.09,397.05 2539.27,397.05 2590.45,397.05 1763.78,444.88 2435.93,448.23 2488.09,448.23 2539.27,448.23 2590.45,448.23 2334.55,449.21 2385.73,449.21 2334.55,499.41 2385.73,499.41 2436.91,499.41 2488.09,499.41 2539.27,499.41 2590.45,499.41 948.82,515.75 1059.06,515.75 1188.98,515.75 1283.46,515.75 2334.55,550.59 2385.73,550.59 2436.91,550.59 2488.09,550.59 2539.27,550.59 2590.45,550.59 2334.55,601.77 2385.73,601.77 2436.91,601.77 2488.09,601.77 2539.27,601.77 2590.45,601.77 795.28,618.11 2334.55,652.95 2385.73,652.95 2436.91,652.95 2488.09,652.95 2539.27,652.95 2590.45,652.95 35.43,681.1 169.29,681.1 1059,699 1280,755 1388,755 1481,755 1059,761 3114.17,830.71 35.43,842.52 35.43,1011.81 2886.5,1063.5 35.43,1185.04 2266.73,1329.72 3114.17,1354.33 35.43,1362.2 2283.46,1402.56 2334.55,1494.55 2385.73,1494.55 2435.93,1494.55 2488.09,1494.55 2539.27,1494.55 2590.45,1494.55 257.6,1520.5 2435.93,1545.73 2488.09,1545.73 2539.27,1545.73 2590.45,1545.73 2334.55,1546.71 2385.73,1546.71 35.43,1570.87 2334.55,1596.91 2385.73,1596.91 2436.91,1596.91 2488.09,1596.91 2539.27,1596.91 2590.45,1596.91 2334.55,1648.09 2385.73,1648.09 2436.91,1648.09 2488.09,1648.09 2539.27,1648.09 2590.45,1648.09 2334.55,1699.27 2385.73,1699.27 2436.91,1699.27 2488.09,1699.27 2539.27,1699.27 2590.45,1699.27 35.43,1744.09 2334.55,1750.45 2385.73,1750.45 2436.91,1750.45 2488.09,1750.45 2539.27,1750.45 2590.45,1750.45 267.72,1850.39 472.44,1850.39 653.54,1850.39 814.96,1850.39 3114.17,1917.32 35.43,1976.38 685.5,2015.5 703.5,2015.5 874,2037 892,2037 3236.22,2039.37 35.43,2212.6 161.42,2283.46 2305.12,2371.06 2642.72,2373.03 2737.2,2373.03 2674.25,2384 2705.75,2384 2642.72,2394.68 2737.2,2394.68 35.43,2421.26 2305.12,2481.3 2195,2494 2213,2494 161.42,2496.06 316.2,2501.3 334.2,2501.3 3236.22,2523.62 2465,2539 35.43,2633.86 988.19,2657.48 1185.04,2657.48 161.42,2669.29 307.09,2688.98 1275.59,2708.66 1397.64,2708.66 1559.06,2708.66 1807.09,2708.66 649.61,2712.6 763.78,2791.34 937.01,2791.34 555.12,2799.21 1944.88,2811.02 358.27,2881.89 515.75,2881.89 442.91,3021.44 3236.22,3027.56 1944.88,3051.18 937.01,3165.35 442.91,3186.07 1944.88,3259.84 442.91,3381.15 3236.22,3405.51 937.01,3444.88 1944.88,3476.38 442.91,3700.79 692.91,3700.79 937.01,3700.79 1944.88,3700.79 2240.16,3700.79 2535.43,3700.79 3236.22,3700.79
  other v2: 2011.81,362.2 2011.81,404.7 2011.81,447.2 2011.81,489.7 2192.91,494.09 2109.25,535.43 2192.91,556.1 2056.1,611.22 2580.71,694.82 1723.51,837.64 1686.97,878.05 1560.98,909.53 1686.97,909.53 1497.99,1067.01 1918.21,1082.83 1918.21,1125.65 1655.46,1129.98 1403.5,1192.99 1882,1230.5 1623.98,1318.98 1340.51,1413.5 2025.59,1428.15 2085.63,1428.15 2042.32,1512.8 2073.82,1551.18 2192.91,1589.63 2044.29,1639.76 2580.71,1792.32
  other v3: 1160.47,1771.69 1425.2,2397.64 1476.38,2397.64 1527.56,2397.64 1425.2,2448.82 1425.2,2500 1425.2,2551.18 1425.2,2602.36 1476.38,2602.36 1527.56,2602.36 580,2995 605,2995 630,2995 655,2995
  other v4: 2161.42,595.47 1750,628.94 2131.89,647.64 2186.02,663.39 2134.84,697.83 1767.72,743.11 1768.7,772.64 1748.03,840.55 1909.45,863.19 1750,903.54 1909.45,904.53
  other v5: 1175.63,3113.13 1215,3113.13 1254.37,3113.13 1175.63,3152.5 1254.37,3152.5 1175.63,3191.87 1215,3191.87 1254.37,3191.87
  other v6: 1877.95,512.8 2037.4,654.53 1871.15,665.39 2026.57,735.24
  other v7: 2305,2409.86 2305,2442.14
GND_OSC0: C147.2 C192.2 C193.2 R176.1 U15.V11 | length 183
  TopLayer - S1 (.GTL) w8: U15.V11@1482.24,862.28 v2@1495,849.54
  TopLayer - S1 (.GTL) w15: C192.2@1408.62,655 v1(1450,655) C193.2@1486.38,655
  BottomLayer - S8 (.GBL) w9.84: v1(1450,655) 1486.38,655 R176.1@1491.38,650
  BottomLayer - S8 (.GBL) w15: v2@1497.5,847.03 v2(1497.95,846.58) 1497.95,889.06 C147.2@1497.5,889.51
GND_RTC: C194.2 C198.2 U15.A5 | length 293.7
  TopLayer - S1 (.GTL) w7.5: C198.2@1171.12,1595 C194.2@1230,1595 ; C194.2@1241.38,1595 C194.2@1230,1595 ; U15.A5@1293.27,1397.72 1293.27,1511.73 1230,1575 C194.2@1230,1595
GNDA_ADC: C144.2 C195.2 C196.2 C197.2 L7.1 U15.A9 U15.E8 | length 292
  TopLayer - S1 (.GTL) w6: 1410,1437.5 1419.25,1428.25 U15.A9@1419.25,1397.72
  TopLayer - S1 (.GTL) w10: C195.2@1355,1504.51 1358.51,1501 C196.2@1382.5,1501 ; v1(1382.5,1479.5) C196.2@1382.5,1501 ; C196.2@1382.5,1504.51 C196.2@1382.5,1501 ; 1410,1437.5 C197.2@1410,1504.51 1406.49,1501 C196.2@1382.5,1501 ; v1@1445,1561 v1(1445.5,1561.5)
  TopLayer - S1 (.GTL) w15: v2(1372.01,1287.48) U15.E8@1387.76,1271.75
  TopLayer - S1 (.GTL) w20: v1(1445.5,1561.5) L7.1@1445.5,1599.5
  BottomLayer - S8 (.GBL) w10: C144.2@1392.5,1380.49 1392.5,1402.5 v2(1403.46,1413.46)
GPIO_PHY_RESETN: R38.1 U11.1 U15.T6 | length 1570.8
  TopLayer - S1 (.GTL) w4.75: v2(1309.02,909.53) U15.T6@1324.75,925.29
  TopLayer - S1 (.GTL) w5.91: R38.1@1878.88,1920 1867.13,1920 v1(1867.13,1888.78) 1867.13,1863.09 U11.1@1880.1,1863.09
  MidLayer5 - S6 (.G5) w4.72: v2(1309.02,909.53) 1324.84,893.7 1599.41,893.7 1608.27,902.56 1608.27,1044.23 1576.77,1075.73 1576.77,1110.24 1639.76,1173.23 1639.76,1319.26 1664.99,1344.49 1706.99,1344.49 1769,1406.5 1769,1436.5 1753,1452.5 1753,1666.39 1867.13,1780.51 v1(1867.13,1888.78)
I2C0_SCL: R117.1 U13.9 U15.C16 U19.6 | length 2305.2
  TopLayer - S1 (.GTL) w4.75: U15.C16@1639.72,1334.72 1656,1351 1656,1425.5 1687,1456.5 1776.5,1456.5 1803,1483 1803,1648.5 1791,1660.5 U19.6@1736.01,1660.5
  TopLayer - S1 (.GTL) w4.92: v1(408.5,2147) 426,2164.5 426,2170 470.63,2214.63 U13.9@480.83,2214.63
  TopLayer - S1 (.GTL) w12: R117.1@1648.62,1655 1654.12,1660.5 v1(1679.5,1660.5) U19.6@1736.01,1660.5
  MidLayer5 - S6 (.G5) w5.91: v1(408.5,2147) 437,2147 440.5,2143.5 510.5,2143.5 670.73,1983.27 742.13,1983.27 1024.61,1700.79 1024.61,1622.05 v1(1004.92,1602.36)
  BottomLayer - S8 (.GBL) w5.91: v1(1004.92,1602.36) 1408.46,1602.36 1466.6,1660.5 v1(1679.5,1660.5)
I2C0_SDA: R118.1 U13.8 U15.C17 U19.5 | length 2388.7
  TopLayer - S1 (.GTL) w4.75: U15.C17@1671.22,1334.72 1686.95,1350.47 1686.95,1429.95 1701.5,1444.5 1781,1444.5 1814,1477.5 1814,1689 1790.5,1712.5 U19.5@1738.01,1712.5 U19.5@1730.51,1712.5
  TopLayer - S1 (.GTL) w4.92: v1(368.5,2147) 390.5,2169 409.5,2169 470.88,2230.38 U13.8@480.83,2230.38
  TopLayer - S1 (.GTL) w12: R118.1@1648.62,1702.5 1653.12,1707 v1(1680,1707) 1725.01,1707 U19.5@1730.51,1712.5
  MidLayer5 - S6 (.G5) w6: v1(368.5,2147) 387.5,2128 437,2128 440.5,2131.5 498.5,2131.5 668.39,1961.61 741.14,1961.61 1004.92,1697.83 v1(1004.92,1642.72)
  BottomLayer - S8 (.GBL) w5.91: 1050.2,1618.11 1401.57,1618.11 1460.12,1676.65 1649.65,1676.65 v1(1680,1707)
  BottomLayer - S8 (.GBL) w6: v1(1004.92,1642.72) 1029.53,1618.11 1050.2,1618.11
JTAG_EMU0: J8.13 R144.2 R152.1 U15.C14 | length 2183
  TopLayer - S1 (.GTL) w4.75: U15.C14@1576.73,1334.72 v2(1592.48,1350.47)
  TopLayer - S1 (.GTL) w5.91: v1(1504.92,1969.49) 1526.67,1991.24 J8.13@1526.67,2075
  TopLayer - S1 (.GTL) w9.84: v1(2138.62,2980) R144.2@2173.5,2980
  MidLayer2 - S3 (.G2) w4.72: v1(1504.92,1969.49) 1545.28,1929.13 1545.28,1363.19 1557.99,1350.47 v2(1592.48,1350.47)
  MidLayer2 - S3 (.G2) w5.91: v1(1504.92,1969.49) 1529.53,1994.09 1529.53,2297.24 1548.23,2315.94 1598.45,2315.94 2119.09,2836.59 2119.09,2960.47 v1(2138.62,2980)
  BottomLayer - S8 (.GBL) w5.91: v1(1504.92,1969.49) 1504.92,1936.2 R152.1@1505,1936.12
JTAG_EMU1: J8.14 R146.1 R147.2 U15.B14 | length 1982.1
  TopLayer - S1 (.GTL) w4.75: U15.B14@1576.73,1366.22 v2(1592.48,1381.97)
  TopLayer - S1 (.GTL) w5.91: J8.14@1537.5,2210.04 1548.23,2220.77 v1(1548.23,2284.45) ; R146.1@2168.88,2812.5 2157.48,2812.5 2157.48,2865 R147.2@2173.5,2865
  TopLayer - S1 (.GTL) w9.84: v1(2138.62,2865) R147.2@2157.48,2865
  MidLayer2 - S3 (.G2) w4.72: v1(1548.23,2284.45) 1548.23,2013.78 1574.8,1987.2 1574.8,1827.76 1556.1,1809.06 1556.1,1492.13 1574.8,1473.43 1574.8,1399.65 v2(1592.48,1381.97)
  MidLayer2 - S3 (.G2) w5.91: v1(1548.23,2284.45) 1567.91,2304.13 1603.35,2304.13 2138.62,2839.41 v1(2138.62,2865)
JTAG_TCK: R139.2 R159.1 R160.1 U15.A12 | length 2534.8
  TopLayer - S1 (.GTL) w4.75: U15.A12@1513.74,1397.76 v2(1529.49,1413.46)
  TopLayer - S1 (.GTL) w9.84: v1(2138.62,3267.5) R139.2@2173.5,3267.5
  MidLayer2 - S3 (.G2) w4.72: v1(1510.83,2284.45) 1510.83,2100.39 1466.54,2056.1 1466.54,1944.88 1529.49,1881.93 v2(1529.49,1413.46)
  MidLayer2 - S3 (.G2) w5.91: v1(1510.83,2284.45) 1510.83,2297.24 1541.34,2327.76 1593.56,2327.76 2107.28,2841.48 2107.28,2977.36 2187.99,3058.07 2187.99,3218.13 v1(2138.62,3267.5)
  BottomLayer - S8 (.GBL) w5.91: R159.1@1430,2104 R160.1@1487.5,2104 1488.19,2104.69 1488.19,2194.88 1510.83,2217.52 v1(1510.83,2284.45)
JTAG_TDI: J8.3 R140.2 U15.B11 | length 2524.5
  TopLayer - S1 (.GTL) w4.75: U15.B11@1482.24,1366.26 v2(1497.99,1381.97)
  TopLayer - S1 (.GTL) w5.91: J8.3@1287.5,2075 1283.46,2070.96 1283.46,1993.11 1294.29,1982.28 1366.14,1982.28 v1(1387.8,1960.63)
  TopLayer - S1 (.GTL) w9.84: v1(2138.62,3210) R140.2@2173.5,3210
  MidLayer2 - S3 (.G2) w4.72: v1(1387.8,1960.63) 1417.75,1930.68 1417.75,1686.95 1413.75,1682.95 1413.75,1546.45 1440.25,1519.95 1440.25,1423.42 1481.7,1381.97 v2(1497.99,1381.97)
  MidLayer2 - S3 (.G2) w5.91: v1(1387.8,1960.63) 1365.16,1983.27 1365.16,2054.13 1458.66,2147.64 1458.66,2327.76 1494.09,2363.19 1578.89,2363.19 2071.85,2856.15 2071.85,3022.64 2119.09,3069.88 2119.09,3190.47 v1(2138.62,3210)
JTAG_TDO: J8.7 R141.2 U15.A11 | length 2287.1
  TopLayer - S1 (.GTL) w4.75: U15.A11@1482.24,1397.76 v2(1497.99,1413.46)
  TopLayer - S1 (.GTL) w5.91: v1(1387.5,2002.26) J8.7@1387.5,2075
  TopLayer - S1 (.GTL) w9.84: v1(2138.62,3152.5) R141.2@2173.5,3152.5
  MidLayer2 - S3 (.G2) w4.72: v1(1387.5,2002.26) 1432.09,1957.68 1432.09,1707.68 1468.5,1671.26 1468.5,1442.95 v2(1497.99,1413.46)
  MidLayer2 - S3 (.G2) w5.91: v1(1387.5,2002.26) 1387.5,2044 1474.41,2130.91 1474.41,2319.88 1505.91,2351.38 1583.78,2351.38 2083.66,2851.26 2083.66,3011.81 2157.48,3085.63 2157.48,3133.64 v1(2138.62,3152.5)
JTAG_TMS: J8.1 R142.2 U15.C11 | length 2484.1
  TopLayer - S1 (.GTL) w4.75: U15.C11@1482.24,1334.76 v2(1497.99,1350.47)
  TopLayer - S1 (.GTL) w5.91: J8.1@1237.5,2075 1237.5,1992.81 1269.68,1960.63 v6(1337.6,1960.63) ; v1(2099.92,3095) R142.2@2173.5,3095
  MidLayer2 - S3 (.G2) w4.72: v6(1337.6,1960.63) 1407,1891.23 1407,1691.41 1403,1687.41 1403,1542 1429.5,1515.5 1429.5,1418.96 v2(1497.99,1350.47)
  MidLayer2 - S3 (.G2) w5.91: v6(1337.6,1960.63) 1324.8,1973.43 1324.8,2066.93 1437.99,2180.12 1437.99,2327.76 1485.24,2375 1573.99,2375 2060.04,2861.05 2060.04,3055.12 v1(2099.92,3095)
JTAG_TRSTN: J8.2 R143.2 R153.2 U15.B10 | length 2469.2
  TopLayer - S1 (.GTL) w4.75: U15.B10@1450.75,1366.22 1466.48,1381.97 1466.48,1410.02 1475,1418.55 1475,1484.96 v2(1497.99,1507.95)
  TopLayer - S1 (.GTL) w5.91: J8.2@1237.5,2210.04 v1(1237.5,2283.96) 1258.66,2305.12 1490.16,2305.12 v1(1510.83,2325.79)
  TopLayer - S1 (.GTL) w9.84: v1(2138.62,3037.5) R143.2@2173.5,3037.5
  MidLayer2 - S3 (.G2) w4.72: v2(1497.99,1507.95) 1481.3,1524.65 1481.3,1563.98 1491.14,1573.82 1491.14,1735.24 1455.71,1770.67 1455.71,2079.72 1489.17,2113.19 1489.17,2304.13 v1(1510.83,2325.79)
  MidLayer2 - S3 (.G2) w5.91: v1(1510.83,2325.79) 1524.61,2339.57 1588.67,2339.57 2095.47,2846.37 2095.47,2994.35 v1(2138.62,3037.5)
  BottomLayer - S8 (.GBL) w5.91: R153.2@1237.5,2251.12 v1(1237.5,2283.96)
MDIO_CLK_1: R73.2 U6.20 | length 1375.4
  TopLayer - S1 (.GTL) w4.75: v1(2531.5,1930) 2551.08,1910.42 U6.20@2551.08,1841
  TopLayer - S1 (.GTL) w4.92: R73.2@1906.62,1043 R73.2@1898.62,1035 v2@1940.44,1035
  MidLayer2 - S3 (.G2) w4.68: v2(1942.47,1037.04) 2093.14,1037.04 2115.1,1059 2462.6,1406.5 2462.6,1791.34 2511.81,1840.55 2511.81,1910.31 v1(2531.5,1930)
MDIO_CLK_2: R72.2 U12.20 | length 818
  TopLayer - S1 (.GTL) w4.75: v1(2531.5,832.5) 2551.08,812.92 U12.20@2551.08,743.5
  MidLayer5 - S6 (.G5) w4.68: v2(1970.47,1014.04) 2349.96,1014.04 v1(2531.5,832.5)
  BottomLayer - S8 (.GBL) w4.92: R72.2@1898.62,1045 1907.62,1036 1929.59,1014.04 v2(1970.47,1014.04)
MDIO_DATA_1: R74.2 U6.21 | length 1329.3
  TopLayer - S1 (.GTL) w4.75: U6.21@2531.5,1839.9 v1(2531.5,1892.5)
  TopLayer - S1 (.GTL) w4.92: R74.2@1906.62,995.5 R74.2@1898.62,987.5 v2@1940.44,987.5
  MidLayer2 - S3 (.G2) w4.68: v2(1942.47,989.54) 2073.2,989.54 2095.16,1011.5 2514.76,1431.1 2514.76,1790.35 2531.5,1807.09 v1(2531.5,1892.5)
MDIO_DATA_2: R75.2 U12.21 | length 782.1
  TopLayer - S1 (.GTL) w4.75: U12.21@2531.5,742.4 v1(2531.5,795)
  MidLayer5 - S6 (.G5) w4.75: 2359.96,966.54 v1(2531.5,795)
  MidLayer5 - S6 (.G5) w4.92: v2(1970.47,966.54) 2359.96,966.54
  BottomLayer - S8 (.GBL) w4.92: R75.2@1907.62,988.5 R75.2@1898.62,997.5 1902.11,997.5 1927.38,972.22 1964.78,972.22 v2(1970.47,966.54)
MICROSD_EARTH: C206.1 J6.9 J6.12 J6.13 J6.14 | length 1845.4
  TopLayer - S1 (.GTL) w11.81: J6.9@662.11,117.5 662.11,140 165,140 140,115 62.99,115 62.99,640 737.5,640 C206.1@737.5,633.62 C206.1@737.5,626.12
MMC1_CLK: J6.5 R123.1 U15.U9 U18.8 | length 1464.8
  TopLayer - S1 (.GTL) w4.75: v2@1401.14,875.69 1419.25,893.8 v2@1403.5,878.06
  TopLayer - S1 (.GTL) w10: v1(604.5,260) 604.5,286.5 618,300 J6.5@655.55,300
  MidLayer2 - S3 (.G2) w4.72: v1(737.78,260) 758.22,239.57 784.45,239.57 796.85,251.97 796.85,320.47 842.26,365.89 842.26,469.39 931.86,558.99 1184.93,558.99 1344.66,718.71 1344.66,846.78 1360.08,862.2 1387.68,862.2 v2(1403.5,878.03)
  BottomLayer - S8 (.GBL) w6: v1(737.78,260) 756.5,278.71 U18.8@756.5,297.48
  BottomLayer - S8 (.GBL) w10: R123.1@563.62,260 v1(604.5,260) v1(737.78,260)
MMC1_CMD: J6.3 R122.1 U15.V9 U18.1 | length 1424.1
  TopLayer - S1 (.GTL) w4.75: v2@1403.5,846.56 U15.V9@1419.25,862.28
  TopLayer - S1 (.GTL) w10: v1(604.5,390) J6.3@655.55,390
  MidLayer2 - S3 (.G2) w4.72: v1(737.76,389.97) 737.76,375.24 752.76,360.24 792.32,360.24 808.07,375.98 808.07,480.91 916.42,589.25 1172.53,589.25 1310.83,727.55 1310.83,779.72 1290.35,800.2 1290.35,856.5 1300.59,866.73 1319.49,866.73 1346.46,893.7 1411.3,893.7 1419,886 1419,862.03 v2(1403.5,846.54)
  BottomLayer - S8 (.GBL) w6: U18.1@737.76,351.57 v1(737.76,389.97)
  BottomLayer - S8 (.GBL) w10: R122.1@563.62,390 v1(604.5,390) v1@737.73,390
MMC1_DAT0: J6.7 R124.1 U15.U7 U18.7 | length 1368.9
  TopLayer - S1 (.GTL) w4.75: U15.U7@1356.23,893.78 v2@1371.98,878.03
  TopLayer - S1 (.GTL) w10: v1(604.5,215) J6.7@655.55,215
  MidLayer2 - S3 (.G2) w4.72: v1(777.13,260) 777.13,329.29 819.29,371.46 819.29,474.02 923.78,578.5 1176.85,578.5 1321.65,723.3 1321.65,822.64 1329.53,830.51 1329.53,854.33 1356.52,881.32 v2@1372,881.32
  BottomLayer - S8 (.GBL) w6: v1@777.95,259.61 U18.7@777.95,298.03
  BottomLayer - S8 (.GBL) w10: R124.1@563.62,215 v1(604.5,215) 732.13,215 v1(777.13,260)
  other v2: 1372.01,878.06
MMC1_DAT1: J6.8 R125.1 U15.V7 U18.6 | length 1378.4
  TopLayer - S1 (.GTL) w4.75: U15.V7@1356.23,862.28 v2(1372.01,846.54)
  TopLayer - S1 (.GTL) w10: v1(604.5,170) 655.55,170 J6.8@658.56,173.01
  MidLayer2 - S3 (.G2) w4.72: v1(816.34,260.04) 816.34,277.76 861.78,323.19 861.78,461.31 939.94,539.47 1193.02,539.47 1364.17,710.63 1364.17,830.71 1367.72,834.25 1367.72,842.24 v2(1372.01,846.54)
  BottomLayer - S8 (.GBL) w4.72: 796.81,279.13 U18.6@796.81,298.43
  BottomLayer - S8 (.GBL) w5.91: 796.81,279.13 v1@815.94,260
  BottomLayer - S8 (.GBL) w10: R125.1@563.62,170 v1(604.5,170) 725.94,170 v1@815.94,260
MMC1_DAT2: J6.1 R120.1 U15.R8 U18.3 | length 1353.3
  TopLayer - S1 (.GTL) w4.75: v2(1372.01,941.02) U15.R8@1387.76,956.77
  TopLayer - S1 (.GTL) w10: v1(604.5,480) J6.1@655.55,480
  MidLayer2 - S3 (.G2) w4.72: v1(778.54,389.76) 778.54,484.54 907.1,613.1 1166.25,613.1 1258.27,705.12 1258.27,854.72 1297.44,893.9 1315.16,893.9 1348.82,927.56 1358.54,927.56 v2(1372.01,941.02)
  BottomLayer - S8 (.GBL) w6: U18.3@777.13,351.57 v1@777.13,388.35
  BottomLayer - S8 (.GBL) w10: R120.1@563.62,480 v1(604.5,480) 731.18,480 777.13,434.06 v1@777.13,388.35
MMC1_DAT3: J6.2 R121.1 U15.T8 U18.2 | length 1408
  TopLayer - S1 (.GTL) w4.75: v2@1372.01,909.55 U15.T8@1387.76,925.28
  TopLayer - S1 (.GTL) w10: v1(604.5,435) J6.2@655.55,435
  MidLayer2 - S3 (.G2) w4.72: v1(737.78,433.5) 757.87,413.41 757.87,384.45 771.26,371.06 786.42,371.06 796.85,381.5 796.85,486.81 910.04,600 1168.21,600 1299.61,731.39 1299.61,770.87 1276.47,794 1276.47,858.36 1297.19,879.08 1315.89,879.08 1348.65,911.84 v2@1372,911.84
  BottomLayer - S8 (.GBL) w6: v1(737.78,433.5) 757.44,413.84 U18.2@757.44,351.57
  BottomLayer - S8 (.GBL) w10: R121.1@563.62,435 v1(604.5,435) 736.28,435 v1(737.78,433.5)
  other v2: 1372,909.53
NetC1_1: C1.1 C2.1 C3.1 C10.1 C14.1 J1.1 L2.2 R6.2 U1.5 | length 3028.9
  TopLayer - S1 (.GTL) w8: R6.2@1021,3022.5 v1(1021,3100.5)
  TopLayer - S1 (.GTL) w12: 1202,3355.5 1202,3265.89 U1.5@1202.2,3265.69
  TopLayer - S1 (.GTL) w60: J1.1@1830,2912.5 1830,2987.5
  BottomLayer - S8 (.GBL) w10: v1(1021,3100.5) 1021,3268 1252.5,3499.5 1776,3499.5 1852,3423.5 1852,2934.5 J1.1@1830,2912.5
  BottomLayer - S8 (.GBL) w12: v1(1202,3392.5) 1259,3449.5 1747,3449.5 1809,3387.5 1809,2933.5 J1.1@1830,2912.5
NetC4_1: C4.1 L2.1 U1.1 U1.2
NetC4_2: C4.2 U1.3 | length 170.2
  TopLayer - S1 (.GTL) w14: U1.3@1253.39,3265.69 1253.39,3332.89 ; 1253.39,3332.89 1270,3349.5 C4.2@1270,3377.5 1253.39,3360.89 1253.39,3332.89
NetC5_1: C5.1 C6.1 C7.1 D1.1 L1.1 R1.1 | length 192.2
  TopLayer - S1 (.GTL) w9.84: R1.1@882.5,3026.5 882.5,3080
  TopLayer - S1 (.GTL) w70.87: 678.74,3128.76 D1.1@678.74,3267.5
NetC8_1: C8.1 C9.1 C11.1 L1.2 R1.2 R2.2 U1.13 U1.14 | length 972.4
  TopLayer - S1 (.GTL) w9.84: 882.5,2907.5 R1.2@882.5,2963.5
  TopLayer - S1 (.GTL) w10: R2.2@1128.62,2817.5 C11.1@1235,2817.5
  TopLayer - S1 (.GTL) w70.87: 606.75,2845.75 735,2717.5 1202.5,2717.5 1247.5,2762.5 C11.1@1247.5,2860
NetC12_1: C12.1 U1.11 | length 160.1
  TopLayer - S1 (.GTL) w10: C12.1@1128.62,2917.5 1160,2917.5 1176.61,2934.11 U1.11@1176.61,3039.31
NetC13_1: C13.1 U1.4 | length 233.9
  TopLayer - S1 (.GTL) w10: C13.1@1161.5,3452.5 1174.5,3439.5 1208,3439.5 1227.8,3419.7 U1.4@1227.8,3265.69
NetC14_2: C14.2 R6.1 R7.2 U1.9
NetC15_1: C15.1 R8.2 U2.1 | length 168.3
  TopLayer - S1 (.GTL) w20: U2.1@1741.61,2401.5 U2.1@1773.5,2401.5
  TopLayer - S1 (.GTL) w31.5: U2.1@1766.73,2398.62 1766.73,2339 R8.2@1843.5,2339
NetC16_1: C16.1 J3.1 U2.2 | length 189.9
  TopLayer - S1 (.GTL) w25: U2.2@1741.61,2451.5 C16.1@1832.01,2451.5 ; J3.1@1932.5,2452.5 J3.1@1935,2450
  TopLayer - S1 (.GTL) w31.5: C16.1@1836.61,2448.82 J3.1@1932.62,2448.82
NetC17_1: C17.1 R10.2 U3.7 | length 40.4
  TopLayer - S1 (.GTL) w11.02: 2233.64,2397.64 2249.2,2413.2 U3.7@2267.6,2413.2
NetC18_1: C18.1 R9.1 R15.2 U3.3 U3.5 | length 463.6
  TopLayer - S1 (.GTL) w10: C18.1@2266.5,2536 C18.1@2279.5,2549 ; U3.3@2342.4,2438.8 2342.61,2439 v1(2373,2439)
  TopLayer - S1 (.GTL) w20: C18.1@2266.5,2536 v3@2266.5,2588.5 ; R15.2@2613.5,2534 v3@2613.5,2666.5
  MidLayer5 - S6 (.G5) w7.87: v3(2276.99,2590) 2343.07,2590 2373,2560.07 v1(2373,2439)
  other v3: 2252.99,2590 2600,2668 2624,2668
NetC21_1: C21.1 R14.1 R16.2 U3.2 | length 195.4
  TopLayer - S1 (.GTL) w12: U3.2@2342.4,2413.2 2383.8,2413.2 2396,2401 2418.62,2401 R14.1@2420,2399.62 C21.1@2420,2448 ; C21.1@2420,2457.38 C21.1@2420,2448 ; R16.2@2465,2457.38 2465,2448 C21.1@2420,2448
NetC24_2: C24.2 R15.1 U5.3 U5.6 | length 450.3
  TopLayer - S1 (.GTL) w10: R15.1@2676.5,2534 v1(2729,2534) ; U5.3@2715.59,2345.61 2715.59,2329.41 v1(2729,2316)
  TopLayer - S1 (.GTL) w12: U5.6@2664.41,2422.39 2664.41,2521.91 R15.1@2676.5,2534
  BottomLayer - S8 (.GBL) w10: v1(2729,2316) 2762.8,2349.8 2762.8,2500.2 v1(2729,2534)
NetC25_1: C25.1 U6.17 | length 49.5
  TopLayer - S1 (.GTL) w11.81: U6.17@2613.5,1865 C25.1@2639,1865
  TopLayer - S1 (.GTL) w12: U6.17@2610.14,1841 U6.17@2610.14,1865
NetC26_1: C26.1 U6.64 | length 49.5
  TopLayer - S1 (.GTL) w11.81: U6.64@2613.5,1380 C26.1@2639,1380
  TopLayer - S1 (.GTL) w12: U6.64@2610.14,1380 U6.64@2610.14,1404
NetC27_1: C27.1 T1.1 | length 82.3
  TopLayer - S1 (.GTL) w12: T1.1@3034.96,1851.87 v1(3087.94,1851.87)
  BottomLayer - S8 (.GBL) w12: C27.1@3058.58,1851.87 v1(3087.94,1851.87)
NetC28_1: C28.1 T1.4 | length 82.3
  TopLayer - S1 (.GTL) w12: T1.4@3034.96,1734.94 v1(3087.94,1734.94)
  BottomLayer - S8 (.GBL) w12: C28.1@3058.58,1734.94 v1(3087.94,1734.94)
NetC29_1: C29.1 T1.7 | length 82.3
  TopLayer - S1 (.GTL) w12: T1.7@3034.96,1618.01 v1(3087.94,1618.01)
  BottomLayer - S8 (.GBL) w12: C29.1@3058.58,1618.01 v1(3087.94,1618.01)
